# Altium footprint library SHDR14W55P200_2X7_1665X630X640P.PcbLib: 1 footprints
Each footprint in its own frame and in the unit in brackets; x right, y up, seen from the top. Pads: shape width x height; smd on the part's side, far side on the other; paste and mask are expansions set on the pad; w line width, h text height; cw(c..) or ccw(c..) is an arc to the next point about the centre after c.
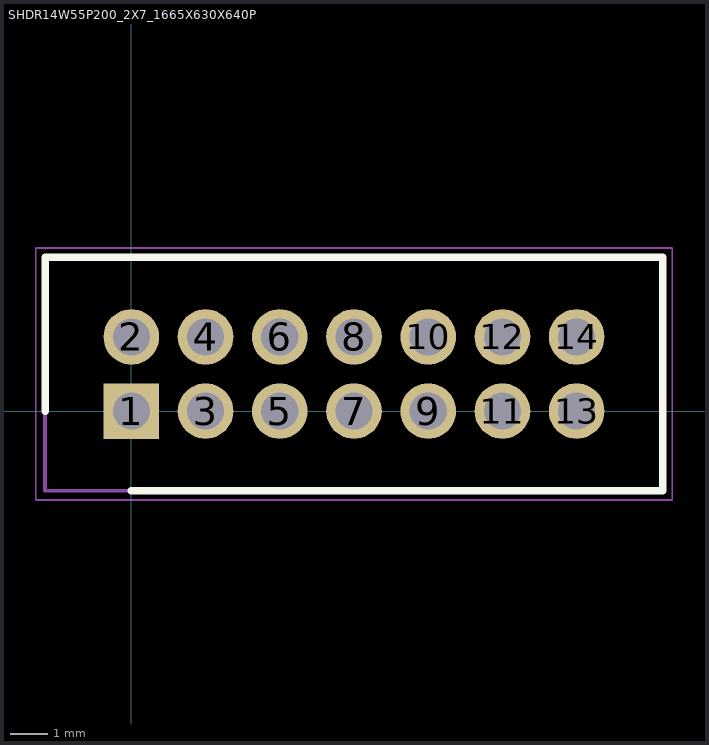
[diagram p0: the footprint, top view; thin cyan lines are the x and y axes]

## SHDR14W55P200_2X7_1665X630X640P [mm]
pads (14):
  rect 1.5x1.5 / inner round 1.5 / far side rect 1.5x1.5 hole 1: 1(0,0)
  round 1.5 hole 1: 2(0,2) 3(2,0) 4(2,2) 5(4,0) 6(4,2) 7(6,0) 8(6,2) 9(8,0) 10(8,2) 11(10,0) 12(10,2) 13(12,0) 14(12,2)
Top Overlay:
  lines w0.2: -2.325,0 -2.325,4.15 14.325,4.15 14.325,-2.15 0,-2.15
Mechanical 15:
  lines w0.1: -2.325,-2.15 -2.325,4.15 14.325,4.15 14.325,-2.15 -2.325,-2.15
Mechanical 20:
  lines w0.05: -2.575,-2.4 -2.575,4.4 14.575,4.4 14.575,-2.4 -2.575,-2.4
